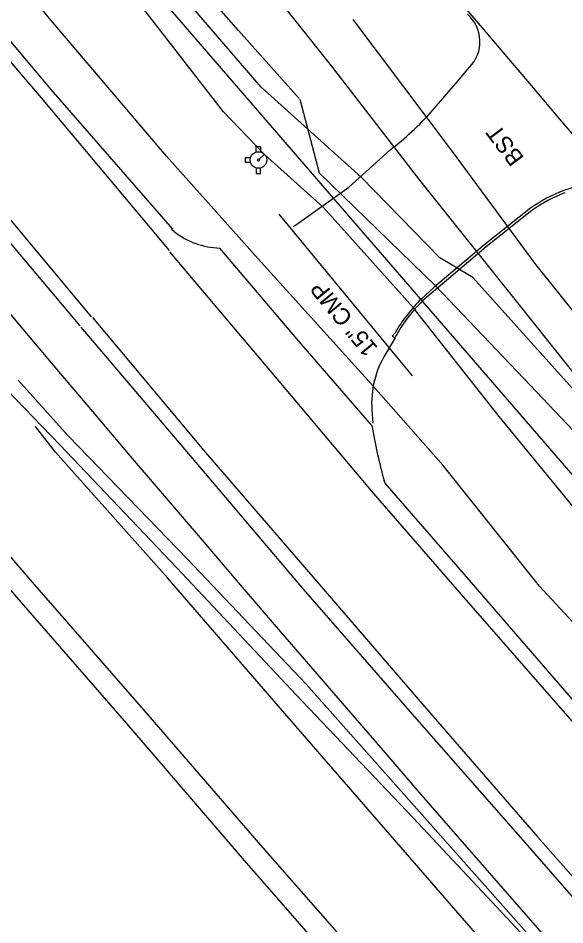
# Model space of a CAD drawing. Extents: x 1263837 to 1268319, y 770628 to 773628.
# Drawn here: x 1266343 to 1266473.4, y 772515.9 to 772731.9 of the extents above; entities that cross this region are included whole.
import ezdxf

# ---------------------------------------------------------------- set-up
doc = ezdxf.new("R2010")
doc.units = 0
for name, color, linetype in [('Exist Roads EOT Text', 7, 'Continuous'), ('Exist Utilities Gas UG Line SUE LOS B', 7, 'Continuous'), ('Exist Utilities Power UG Cable SUE LOS B', 7, 'Continuous'), ('Exist Utilities Telephone UG Cable SUE LOS B', 7, 'Continuous'), ('Exist Utilities Telephone UG FO SUE LOS B', 7, 'Continuous'), ('Exist Utilities TV UG Cable SUE LOS B', 7, 'Continuous'), ('Exist Utilities Water Fire Hydrant CELL', 7, 'Continuous'), ('Exist Utilities Water UG Line SUE LOS B', 7, 'Continuous'), ('Prop Drainage Structure Pipe RCP 15in Class III Label', 7, 'Continuous'), ('Prop Drainage Structure Pipe RCP 24in Class III Label', 7, 'Continuous'), ('Prop Horizontal Alignment', 7, 'Continuous'), ('Prop SS Fill Line', 7, 'Continuous'), ('Prop SS Fill Text', 7, 'Continuous'), ('Prop SS Transition Line', 7, 'Continuous'), ('Scratch_Level_2', 7, 'Continuous'), ('Scratch_Level_5', 7, 'Continuous')]:
    doc.layers.add(name, color=color, linetype=linetype)

# ---------------------------------------------------------------- blocks, each defined once
blk = doc.blocks.new('EXIST UTILITIES WATER FIRE HYDRANT')
at = {"layer": 'Exist Utilities Water Fire Hydrant CELL'}
blk.add_line((0, 0), (0, 0), dxfattribs=at)
for points in [[(-0.01025, 0.03825), (-0.01025, 0.064), (0.01025, 0.064), (0.01025, 0.03775)], [(-0.03825, 0.01025), (-0.064, 0.01025), (-0.064, -0.01025), (-0.03825, -0.01025)], [(-0.01025, -0.03825), (-0.01025, -0.064), (0.01025, -0.064), (0.01025, -0.03775)]]:
    blk.add_lwpolyline(points, dxfattribs=at)
for radius in [0.03954, 0.00485]:
    blk.add_circle((0, 0), radius, dxfattribs=at)

msp = doc.modelspace()

# ---------------------------------------------------------------- linework, layer by layer
at = {"layer": 'Exist Utilities Gas UG Line SUE LOS B'}
msp.add_lwpolyline([(1266626.3, 772417.63), (1266595.05, 772451.72), (1266564.52, 772485.15), (1266536.37, 772515.71), (1266507.66, 772549.98), (1266489.93, 772572.2), (1266467.35, 772596.54), (1266444.35, 772625.31), (1266427.08, 772644.86), (1266400.21, 772674.59), (1266378.42, 772699.08), (1266350.53, 772731.88), (1266329.01, 772758.07), (1266302.33, 772792.31)], dxfattribs=at)
at = {"layer": 'Exist Utilities Power UG Cable SUE LOS B'}
msp.add_lwpolyline([(1266518.15, 772604.61), (1266510.56, 772607.39), (1266486.8, 772633.2), (1266461.84, 772664.46), (1266438.76, 772693.35), (1266417.71, 772720.59), (1266394.19, 772750.17), (1266376.27, 772773.54), (1266353.97, 772806.02), (1266338.19, 772829.96), (1266316.23, 772859.15), (1266292.65, 772887.5), (1266267.51, 772920.13), (1266239.14, 772953.7), (1266230.24, 772964.93), (1266247.17, 772989.49), (1266261.14, 773015.77), (1266284.95, 773046.23)], dxfattribs=at)
at = {"layer": 'Exist Utilities Telephone UG Cable SUE LOS B'}
msp.add_lwpolyline([(1266518.7, 772602.97), (1266516.62, 772609.67), (1266492.26, 772641.05), (1266466.48, 772673.22), (1266446.59, 772700.16), (1266422.87, 772731.65)], dxfattribs=at)
at = {"layer": 'Exist Utilities Telephone UG FO SUE LOS B'}
msp.add_lwpolyline([(1266480.79, 772637.46), (1266451.43, 772670.13), (1266443.59, 772674.8), (1266424.84, 772694.05), (1266400.93, 772715.49), (1266374.32, 772746.45), (1266346.23, 772778.43), (1266332.16, 772795.61), (1266324.39, 772799.33), (1266312.77, 772795.13), (1266304.86, 772796.49)], dxfattribs=at)
at = {"layer": 'Exist Utilities TV UG Cable SUE LOS B'}
for points in [[(1266410.05, 772712.78), (1266395.52, 772728.97), (1266376.18, 772751.05), (1266350.95, 772780.9), (1266333.17, 772804.35), (1266326.13, 772805.33), (1266309.36, 772798.65), (1266282.7, 772832.79), (1266257.31, 772864.32), (1266232.74, 772892.24), (1266212.32, 772919.89), (1266197.07, 772944.48), (1266210.39, 772957.77), (1266229.77, 772978.15), (1266241.16, 772993.4)], [(1266489.88, 772618.38), (1266465.14, 772644.38), (1266442.52, 772668.16), (1266414.85, 772694.99), (1266410.24, 772712.53)]]:
    msp.add_lwpolyline(points, dxfattribs=at)
at = {"layer": 'Exist Utilities Water UG Line SUE LOS B'}
msp.add_line((1266401.71, 772699.47), (1266400.32, 772698.14), dxfattribs=at)
msp.add_lwpolyline([(1266860.23, 772190.35), (1266743.83, 772310), (1266721.02, 772333.68), (1266700.48, 772357.81), (1266674.55, 772384.08), (1266657.31, 772405.72), (1266637.24, 772428.83), (1266608.73, 772461.68), (1266579.07, 772495.61), (1266550.65, 772529.02), (1266522.97, 772560), (1266502.6, 772584.94), (1266480.26, 772609.52), (1266457.73, 772637.02), (1266437.21, 772662.96), (1266415.86, 772686.78), (1266401.76, 772699.43), (1266391.98, 772709.63), (1266367.75, 772740.95), (1266339.94, 772773.71), (1266307.71, 772809.46)], dxfattribs=at)
at = {"layer": 'Prop Drainage Structure Pipe RCP 15in Class III Label'}
msp.add_line((1266405.18, 772685.2), (1266436.96, 772646.69), dxfattribs=at)
at = {"layer": 'Prop Horizontal Alignment'}
msp.add_arc((1275094.23, 780056.99), 11329.16, 216.983333, 223.309327, dxfattribs=at)
at = {"layer": 'Prop SS Fill Line'}
for p, q in [((1266447.74, 772716.83), (1266450.62, 772720.24)), ((1266447.74, 772716.83), (1266450.62, 772720.24)), ((1266447.74, 772716.83), (1266450.62, 772720.24)), ((1266447.74, 772716.83), (1266450.62, 772720.24)), ((1266441.75, 772709.83), (1266447.74, 772716.83)), ((1266441.75, 772709.83), (1266447.74, 772716.83)), ((1266441.75, 772709.83), (1266447.74, 772716.83)), ((1266441.75, 772709.83), (1266447.74, 772716.83)), ((1266433.29, 772656.55), (1266432.91, 772656.02)), ((1266433.29, 772656.55), (1266432.91, 772656.02)), ((1266433.29, 772656.55), (1266432.91, 772656.02)), ((1266433.29, 772656.55), (1266432.91, 772656.02))]:
    msp.add_line(p, q, dxfattribs=at)
for points in [[(1266408.56, 772682.31), (1266409.16, 772682.58), (1266421.87, 772691.68), (1266431.63, 772700.49)], [(1266408.56, 772682.31), (1266409.16, 772682.58), (1266421.87, 772691.68), (1266431.63, 772700.49)], [(1266408.56, 772682.31), (1266409.16, 772682.58), (1266421.87, 772691.68), (1266431.63, 772700.49)], [(1266408.56, 772682.31), (1266409.16, 772682.58), (1266421.87, 772691.68), (1266431.63, 772700.49)], [(1266465.51, 772686.09), (1266454.6, 772677.41), (1266442.5, 772667.22), (1266439.45, 772664.55)], [(1266465.51, 772686.09), (1266454.6, 772677.41), (1266442.5, 772667.22), (1266439.45, 772664.55)], [(1266465.51, 772686.09), (1266454.6, 772677.41), (1266442.5, 772667.22), (1266439.45, 772664.55)], [(1266465.51, 772686.09), (1266454.6, 772677.41), (1266442.5, 772667.22), (1266439.45, 772664.55)]]:
    msp.add_lwpolyline(points, dxfattribs=at)
for centre, major_axis, ratio, start_param, end_param in [((1266444.52, 772726.34), (2.84, -8.15), 0.998393, 0.450267, 2.093141), ((1266444.52, 772726.34), (2.84, -8.15), 0.998393, 0.450267, 2.093141), ((1266444.52, 772726.34), (2.84, -8.15), 0.998393, 0.450267, 2.093141), ((1266444.52, 772726.34), (2.84, -8.15), 0.998393, 0.450267, 2.093141), ((1266386.9, 772759.35), (21.13, 70.99), 0.997162, 4.082043, 4.268421), ((1266386.9, 772759.35), (21.13, 70.99), 0.997162, 4.082043, 4.268421), ((1266386.9, 772759.35), (21.13, 70.99), 0.997162, 4.082043, 4.268421), ((1266386.9, 772759.35), (21.13, 70.99), 0.997162, 4.082043, 4.268421), ((1266485.94, 772657.58), (-13.59, 32.34), 0.99962, 6.251617, 6.507022), ((1266485.94, 772657.58), (-13.59, 32.34), 0.99962, 6.251617, 6.507022), ((1266485.94, 772657.58), (-13.59, 32.34), 0.99962, 6.251617, 6.507022), ((1266485.94, 772657.58), (-13.59, 32.34), 0.99962, 6.251617, 6.507022), ((1266463.01, 772639.84), (-6.17, -33.71), 0.994194, 4.08676, 4.382812), ((1266463.01, 772639.84), (-6.17, -33.71), 0.994194, 4.08676, 4.382812), ((1266463.01, 772639.84), (-6.17, -33.71), 0.994194, 4.08676, 4.382812), ((1266463.01, 772639.84), (-6.17, -33.71), 0.994194, 4.08676, 4.382812)]:
    msp.add_ellipse(centre, major_axis=major_axis, ratio=ratio, start_param=start_param, end_param=end_param, dxfattribs=at)
at = {"layer": 'Prop SS Fill Text'}
for p, q in [((1266478.89, 772692.69), (1266473.15, 772690.89)), ((1266380.25, 772681.09), (1266379.62, 772681.54)), ((1266409.43, 772655.48), (1266391.11, 772677.16)), ((1266427.37, 772634.89), (1266409.43, 772655.48)), ((1266427.35, 772638.58), (1266427.6, 772635.45))]:
    msp.add_line(p, q, dxfattribs=at)
for points in [[(1265928.52, 773196.42), (1265955.6, 773161.07), (1265974.34, 773136.13), (1266000.44, 773102.54), (1266023.03, 773073.42), (1266047.77, 773041.92), (1266068.94, 773014.11), (1266096.74, 772979.15), (1266112.05, 772959.2), (1266136.44, 772928.51), (1266159.7, 772899.76), (1266187.77, 772864.17), (1266215.24, 772830.51), (1266241.66, 772797.95), (1266271.46, 772761.84), (1266300.38, 772726.95), (1266327.38, 772694.6), (1266357.7, 772658.6)], [(1266323.99, 772746.86), (1266350.83, 772714.9), (1266379.86, 772681.67)], [(1266465.17, 772686.64), (1266454.34, 772678.05), (1266442.1, 772667.76), (1266439.11, 772665.01)], [(1266357.93, 772658.32), (1266385.38, 772626.03), (1266411, 772595.83), (1266436.95, 772566.08), (1266464.45, 772534.8), (1266491.83, 772503.51), (1266517.83, 772474.24), (1266545.36, 772443.5), (1266571, 772414.52), (1266597.22, 772385.79), (1266624.11, 772356.56), (1266650.47, 772328.11), (1266677.92, 772297.91), (1266705.75, 772268.47), (1266733.32, 772238.6), (1266758.76, 772211.82)], [(1266432.89, 772656.98), (1266432.19, 772656.15), (1266432.89, 772655.75), (1266430.65, 772652.02)], [(1266731.93, 772218.84), (1266707.53, 772244.78), (1266679.39, 772276.43), (1266651.68, 772306.11), (1266626.62, 772332.88), (1266598.52, 772363.96), (1266570.46, 772395.59), (1266545.53, 772423.39), (1266519.16, 772453.31), (1266491.84, 772483.47), (1266466.11, 772511.86), (1266438.68, 772542.82), (1266411.66, 772573.21), (1266383.41, 772603.04), (1266354.94, 772632.37), (1266343.05, 772645.66)], [(1266317.66, 772623.29), (1266342.19, 772594.53), (1266368.84, 772563.85), (1266396.95, 772531.19), (1266423.69, 772500.53), (1266451.34, 772469.08), (1266485.04, 772430.62), (1266513.92, 772398.56), (1266542.2, 772366.82), (1266568.73, 772337.14), (1266597.4, 772305.79), (1266627.45, 772273.2), (1266656.25, 772242.01), (1266683.72, 772211.17), (1266699.81, 772190.48)], [(1266617.67, 772409.79), (1266590.81, 772438.68), (1266561.79, 772471.1), (1266532.71, 772503.87), (1266504.74, 772535.77), (1266477.39, 772567.05), (1266451.01, 772597.54), (1266430.52, 772621.09), (1266430.29, 772621.69)]]:
    msp.add_lwpolyline(points, dxfattribs=at)
for centre, major_axis, ratio, start_param, end_param in [((1266485.99, 772657.27), (-36.03, -1.44), 0.997675, 5.036573, 5.287997), ((1266391.6, 772695.49), (0.99, -18.31), 0.999074, 5.560875, 6.202488), ((1266466.49, 772637.08), (-10.66, -37.88), 0.991747, 4.194999, 4.454055), ((1266450.26, 772640.08), (3.89, -22.63), 0.999768, 3.995516, 4.60776), ((1266553.2, 772655.83), (-127.08, -11.15), 0.999307, 0.077419, 0.183516)]:
    msp.add_ellipse(centre, major_axis=major_axis, ratio=ratio, start_param=start_param, end_param=end_param, dxfattribs=at)
at = {"layer": 'Prop SS Transition Line'}
for points in [[(1265951.1, 773213.35), (1265978.42, 773176.6), (1265997.02, 773153.03), (1266022.4, 773120), (1266044.65, 773090.78), (1266069.51, 773058.32), (1266091.23, 773031.16), (1266119.47, 772995.3), (1266134.06, 772977.06), (1266160.18, 772943.7), (1266181.04, 772918.53), (1266210.29, 772881.31), (1266236.57, 772849.23), (1266263.03, 772815.74), (1266292.51, 772780.33), (1266321.33, 772744.69), (1266348.53, 772712.94), (1266379.06, 772676.58)], [(1265931.75, 773198.41), (1265958.44, 773163.08), (1265977.34, 773138.21), (1266002.74, 773104.7), (1266026, 773075.89), (1266049.89, 773043.76), (1266071.92, 773016.05), (1266099.33, 772981.13), (1266115.17, 772961.77), (1266138.92, 772930.58), (1266163.31, 772902.93), (1266190.56, 772866.23), (1266218.32, 772833.09), (1266244.06, 772800), (1266274.56, 772764.58), (1266302.88, 772729.04), (1266330.2, 772696.89), (1266360.46, 772660.78)], [(1266851.72, 772155.98), (1266819.92, 772189.69), (1266786.94, 772222.96), (1266757.5, 772254.98), (1266725.07, 772288.17), (1266696.51, 772318.01), (1266668.57, 772348.72), (1266639.44, 772380.36), (1266614.35, 772407.49), (1266588.12, 772436.47), (1266559.63, 772468.18), (1266530.4, 772501.01), (1266501.55, 772533.83), (1266474.61, 772564.96), (1266448.23, 772595.11), (1266427.72, 772618.77), (1266404.36, 772646.43), (1266379.16, 772676.28)], [(1266360.72, 772660.64), (1266387.72, 772628.4), (1266413.72, 772598.24), (1266439.31, 772568.51), (1266466.94, 772536.77), (1266494, 772506.06), (1266519.96, 772476.42), (1266547.43, 772445.84), (1266573.43, 772416.92), (1266599.9, 772387.74), (1266626.38, 772358.75), (1266652.81, 772330.12), (1266681.04, 772299.87), (1266708.27, 772270.61), (1266731.59, 772245.95)], [(1266686.26, 772266.69), (1266678.6, 772275.02), (1266650.45, 772305.15), (1266625.62, 772332.13), (1266597.49, 772363.17), (1266569.25, 772394.78), (1266544.52, 772422.77), (1266518.06, 772452.56), (1266491.14, 772482.87), (1266465.35, 772511.32), (1266437.19, 772541.37), (1266409.28, 772570.7), (1266380.87, 772600.95), (1266352.99, 772630.27), (1266340.44, 772643.31)], [(1266809.83, 772121.27), (1266782.84, 772150.52), (1266751.12, 772184.26), (1266724.47, 772211.55), (1266699.88, 772238.14), (1266671.77, 772267.9), (1266643.1, 772298.58), (1266617.84, 772326.26), (1266589.91, 772356.9), (1266561.22, 772388.93), (1266536.81, 772416.44), (1266510.08, 772446.52), (1266483.84, 772477.3), (1266458.35, 772506.64), (1266431.75, 772537.3), (1266405.57, 772567.42), (1266378.67, 772598.59), (1266351.89, 772628.52), (1266347.17, 772634.59)], [(1266321.52, 772626.36), (1266345.83, 772598.2), (1266372.91, 772567.07), (1266400.81, 772534.87), (1266427.55, 772504.36), (1266455.23, 772472.55), (1266489.18, 772434.7), (1266517.18, 772402.1), (1266545.3, 772370.2), (1266572.03, 772340.1), (1266600.67, 772308.65), (1266630.37, 772276.16), (1266659.22, 772245.03), (1266687.45, 772214.42), (1266705.1, 772194.29)]]:
    msp.add_lwpolyline(points, dxfattribs=at)
at = {"layer": 'Scratch_Level_2'}
msp.add_arc((1275094.23, 780056.99), 11459.16, 216.983333, 225.433333, dxfattribs=at)
at = {"layer": 'Scratch_Level_5'}
msp.add_line((1266484.76, 772611.98), (1266251.71, 772881.81), dxfattribs=at)

# ---------------------------------------------------------------- block references
at = {"layer": 'Exist Utilities Water Fire Hydrant CELL', "xscale": 50, "yscale": 50}
msp.add_blockref('EXIST UTILITIES WATER FIRE HYDRANT', (1266400.32, 772698.14), dxfattribs=at)

# ---------------------------------------------------------------- texts
at = {"layer": 'Exist Roads EOT Text'}
msp.add_text('BST', height=4, rotation=126.9057, dxfattribs=at).set_placement((1266463.8, 772698.66))
at = {"layer": 'Prop Drainage Structure Pipe RCP 24in Class III Label'}
msp.add_text('15" CMP', height=4, rotation=129.5311, dxfattribs=at).set_placement((1266428.93, 772653.39))

doc.saveas('drawing.dxf')
